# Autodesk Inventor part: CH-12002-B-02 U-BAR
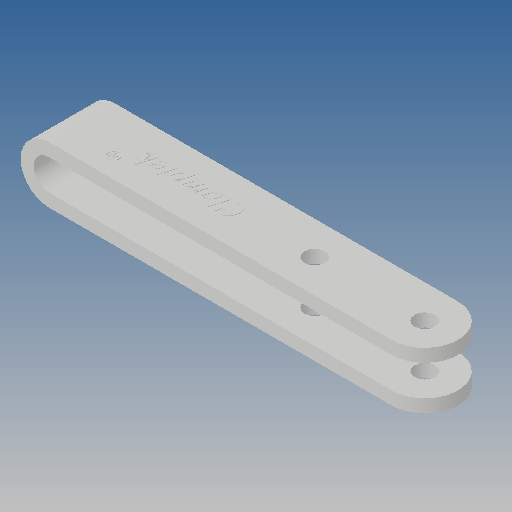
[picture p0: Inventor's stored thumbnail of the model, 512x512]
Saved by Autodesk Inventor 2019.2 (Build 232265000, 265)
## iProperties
Created: 2012-09
Part Number: CH-12002-B-02 U-BAR
Material: Ogólny
Document SubType Name: Modeling
Designer: CADENGINEERING4
Density: 1 g/cm^3
Appearance: Domyślna
Author: CADENGINEERING4
Revision Number: ÈÎºÎ
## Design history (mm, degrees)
feature "ÇÐ³ý-À­Éì5"
node "Bryła1"
